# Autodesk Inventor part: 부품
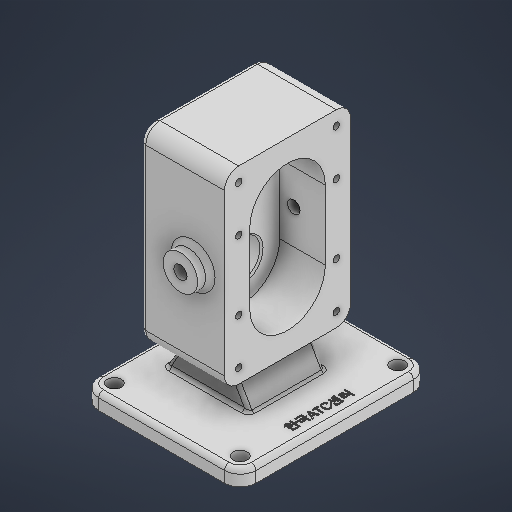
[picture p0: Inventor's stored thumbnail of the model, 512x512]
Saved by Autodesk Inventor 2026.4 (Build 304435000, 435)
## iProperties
Created: 2026-10
Part Number: 부품
Material: 일반
Document SubType Name: Modeling
Designer: user
Density: 1 g/cm^3
Appearance: 기본값
Author: user
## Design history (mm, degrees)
sketch "스케치1"
  geometry: L1 (50, 60)-(-50, 60); L2 (-50, 60)-(-50, -60); L3 (-50, -60)-(50, -60); L4 (50, -60)-(50, 60); L5 (50, 60)-(-50, -60); L6 (-50, 60)-(50, -60); 1 further point
  constraints: 12 end point, 2 midpoint, 2 parallel, 1 horizontal, 1 perpendicular
  dimensions: "d0" = 100 distance of L3.end L2.end; "d1" = 120 distance of L2.end L1.end
extrude "돌출1" new body sketch "스케치1" distance "d2" = 10; taper "d3" = 0 deg
sketch "스케치3"
  geometry: L1 (-33, 30)-(20, 30); L2 (20, 30)-(20, 150); L3 (20, 150)-(-33, 150); L4 (-33, 150)-(-33, 30); L5 (-33, 30)-(20, 150); L6 (20, 30)-(-33, 150); L7 (50, 0)-(-50, 0) reference; L8 (50, 10)-(-50, 10) reference; L9 (-33, 10)-(-16.996, 37.719); L10 (20, 10)-(5.255, 35.539); L11 (-50, 0)-(-50, 10) reference; L12 (20, 10)-(-33, 10); 7 further points
  constraints: 18 end point, 5 midpoint, 2 parallel, 2 point on line, 1 collinear, 1 horizontal, 1 perpendicular, 1 vertical alignment
  dimensions: "d5" = 53 distance of L2.end L3.end; "d6" = 120 distance of L3.end L1.start; "d7" = 150 distance between parallel lines of L7 L3; "d16" = 60 deg angle of L8 L10; "d17" = 17 horizontal distance of point (-50, 5) L9.start; "d18" = 53 distance of L10.start L9.start; "d19" = 60 deg angle of L8 L9
extrude "돌출2" join sketch "스케치3" stored distance "d8" = 80; taper "d9" = 0 deg
sketch "스케치4"
  geometry: L1 (40, 82)-(40, 38); L2 (16, 82)-(16, 38); L3 (64, 38)-(64, 82); L4 (-20, -30)-(100, -30) reference; A1 r 24 centre (40, 82) between (64, 82) and (16, 82); A2 r 24 centre (40, 38) between (16, 38) and (64, 38); 4 further points
  constraints: 8 end point, 4 point on circle, 4 tangent, 3 midpoint, 2 centre point, 1 parallel, 1 vertical, 1 vertical alignment
  dimensions: "d10" = 48 distance between parallel lines of L3 L2; "d11" = 90 distance of point (40, -30) point (40, 60); "d12" = 44 distance of L1.end L1.start
extrude "돌출3" cut sketch "스케치4" distance "d13" = 29; taper "d14" = 0 deg
sketch "스케치5"
  geometry: 1 further point
extrude "돌출4" join sketch "스케치3" stored distance "d20" = 48; taper "d21" = 0 deg
sketch "스케치6"
  geometry: L1 (20, 136)-(20, 112) reference; L2 (20, 68)-(20, 44) reference; L3 (20, 112)-(-50, 112); L4 (20, 68)-(-9, 68) reference; L5 (20, 68)-(-33, 68); L6 (-9, 124.5)-(-24, 124.5); L7 (-24, 124.5)-(-24, 120.5); L8 (-24, 120.5)-(-42.7, 120.5); L9 (-33, 150)-(-33, 30) reference; L10 (-9, 136)-(-9, 112) reference; L11 (20, 30)-(20, 150) reference; L12 (-42.7, 120.5)-(-42.7, 125.5); L13 (-43.2, 126)-(-50, 126); L14 (-50, 131)-(-33, 131); L15 (-50, 131)-(-50, 112); L16 (-9, 124.5)-(-9, 112); L17 (-50, 112)-(-9, 112); L18 (-9, 68)-(-9, 112) reference; L19 (-9, 80.5)-(-24, 80.5); L20 (-24, 80.5)-(-24, 68); L21 (-24, 68)-(-9, 68); L22 (-9, 68)-(-9, 44) reference; L23 (-9, 68)-(-9, 80.5); A1 r 0.5 centre (-43.2, 125.5) between (-42.7, 125.5) and (-43.2, 126); 5 further points
  constraints: 30 end point, 10 point on line, 7 perpendicular, 3 collinear, 2 horizontal, 2 point on circle, 2 tangent, 2 vertical, 1 centre point
  dimensions: "d22" = 25 diameter of L6 L3; "d23" = 15 distance of L6.start L6.end; "d24" = 17 diameter of L8 L3; "d26" = 28 diameter of L13 L3; "d27" = 38 diameter of L14 L3; "d28" = 70 distance between parallel lines of L11 L15; "d29" = 7.3 distance of point (-42.7, 126) L13.end; "d30" = 0.5 radius of A1; "d33" = 25 diameter of L19 L5; "d34" = 15 distance of L19.start L19.end
revolve "회전1" stored, may be unused: angle "d31" = 90 deg
revolve "회전2" stored, may be unused: angle "d32" = 90 deg
revolve "회전3" stored, may be unused: angle "d35" = 90 deg
chamfer "모따기1" distance "d36" = 1; stored, may be unused: second distance "d37" = 2, angle "d38" = 45 deg
chamfer "모따기2" distance "d39" = 0.7; stored, may be unused: second distance "d40" = 2, angle "d41" = 30 deg
chamfer "모따기3" distance "d42" = 1; stored, may be unused: second distance "d43" = 2, angle "d44" = 30 deg
sketch "스케치8"
  geometry: L1 (-50, 0)-(50, 0) reference; L2 (-20, 150)-(-20, 30) reference; C1 r 11 at (0, 90); 4 further points
  constraints: 3 midpoint, 2 vertical alignment, 1 centre point, 1 horizontal alignment
  dimensions: "d45" = 22 diameter of C1
extrude "돌출5" join sketch "스케치8" distance "d46" = 8; taper "d47" = 0 deg
sketch "스케치9"
  geometry: C1 r 11 at (0, 0) reference; 2 further points
  constraints: 1 coincident
hole "구멍1" sketch "스케치9" at (0, 0) diameter "d48" = 8; stored, may be unused: countersink angle "d54" = 90 deg, drill point angle "d56" = 0 deg; dims "d49" = 7.4, "d50" = 0.62479, "d51" = 7.985, "d52" = 4, "d53" = 2, "d55" = 11.9
sketch "스케치10"
  geometry: C1 r 11 at (0, 0) reference; 2 further points
  constraints: 1 coincident
hole "구멍2" sketch "스케치10" at (0, 0) diameter "d57" = 8; stored, may be unused: countersink angle "d63" = 90 deg, drill point angle "d65" = 0 deg; dims "d58" = 7.4, "d59" = 0.62479, "d60" = 7.985, "d61" = 4, "d62" = 2, "d64" = 8
fillet "모깎기1" dims "d66" = 3
sketch "스케치11"
  geometry: L1 (9, 9)-(71, 9); L2 (71, 9)-(71, 111); L3 (71, 111)-(9, 111); L4 (9, 111)-(9, 9); L5 (9, 9)-(71, 111); L6 (71, 9)-(9, 111); L7 (-20, -30)-(100, -30) reference; L8 (64, 82)-(64, 38) reference; L9 (9, 38)-(71, 38); L10 (71, 38)-(71, 82); L11 (71, 82)-(9, 82); L12 (9, 82)-(9, 38); L13 (9, 38)-(71, 82); L14 (71, 38)-(9, 82); 4 further points
  constraints: 24 end point, 6 midpoint, 4 parallel, 2 horizontal, 2 perpendicular, 1 horizontal alignment, 1 point on line, 1 vertical alignment
  dimensions: "d67" = 62 distance of L2.end L3.end; "d68" = 44 distance between parallel lines of L9 L11; "d69" = 29 distance between parallel lines of L11 L3
hole "구멍3" sketch "스케치11" at (9, 111), (71, 111), (9, 82), (71, 82), (71, 38), (9, 38), (71, 9), (9, 9) diameter "d70" = 4.134; stored, may be unused: countersink angle "d74" = 90 deg, drill point angle "d76" = 118 deg; dims "d71" = 10, "d72" = 4, "d73" = 2, "d75" = 12
fillet "모깎기2" dims "d77" = 10
sketch "스케치13"
  geometry: A1 r 10 centre (40, -50) between (40, -60) and (50, -50) reference; A2 r 10 centre (40, 50) between (50, 50) and (40, 60) reference; A3 r 10 centre (-40, 50) between (-40, 60) and (-50, 50) reference; A4 r 10 centre (-40, -50) between (-50, -50) and (-40, -60) reference; 5 further points
  constraints: 4 coincident
hole "구멍4" sketch "스케치13" at (40, -50), (40, 50), (-40, 50), (-40, -50) diameter "d78" = 9; stored, may be unused: countersink angle "d82" = 90 deg, drill point angle "d84" = 0 deg; dims "d79" = 10, "d80" = 4, "d81" = 2, "d83" = 9
fillet "모깎기3" dims "d85" = 3
fillet "모깎기4" dims "d86" = 2
fillet "모깎기5" dims "d87" = 9
fillet "모깎기6" dims "d88" = 3
sketch "스케치14" dims "d0" = 100, "d1" = 120
  geometry: L1 (50, -50)-(50, 50) reference; 3 further points
  constraints: 1 horizontal alignment, 1 midpoint, 1 other
  dimensions: "d89" = 10 distance from line of L1 point (40, 0)
feature "엠보싱1" sketch "스케치14" dims "d0" = 100, "d1" = 120, "d90" = 0.5, "d91" = 0
feature "ў耀Ѡ耀Ѣ耀Ѥ耀Ѧ耀Ѩ耀Ѫ耀Ѭ耀" dims "d0" = 100, "d1" = 120, "d2" = 10, "d3" = 0, "d5" = 53, "d6" = 120, "d7" = 150, "d8" = 80, "d9" = 0, "d10" = 48, "d11" = 90, "d12" = 44, "d13" = 29, "d14" = 0, "d16" = 60 deg, "d17" = 17, "d18" = 53, "d19" = 60 deg, "d20" = 48, "d21" = 0, "d22" = 25, "d23" = 15, "d24" = 17, "d26" = 28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
node "솔리드1"
mirror "미러1"
